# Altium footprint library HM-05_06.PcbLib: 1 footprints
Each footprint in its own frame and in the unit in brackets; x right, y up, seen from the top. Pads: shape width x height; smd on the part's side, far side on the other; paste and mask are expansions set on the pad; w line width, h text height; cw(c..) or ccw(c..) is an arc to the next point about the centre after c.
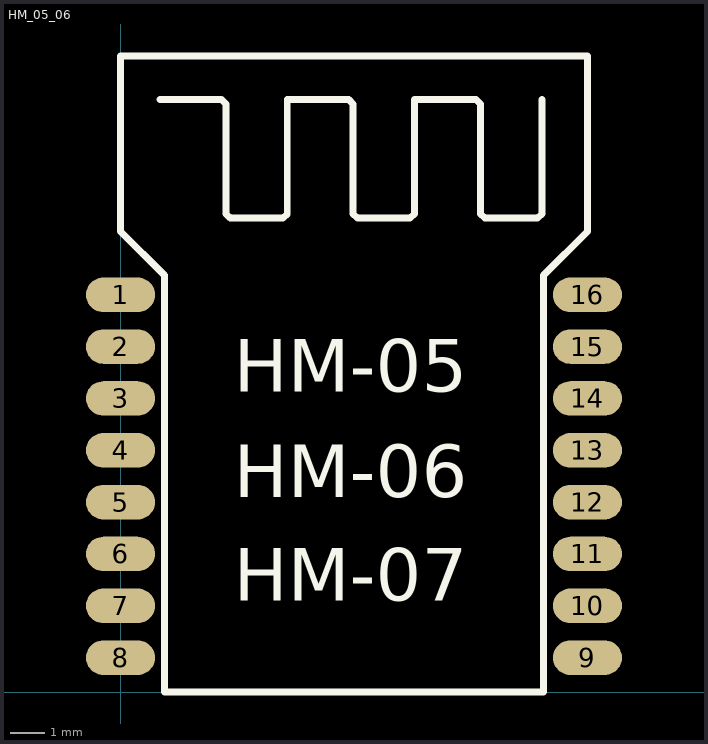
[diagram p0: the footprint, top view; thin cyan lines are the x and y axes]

## HM_05_06 [mm] "www.jnhuamao.cn"
pads (16):
  oval 2x1 smd: 1(0,11.5) 2(0,10) 3(0,8.5) 4(0,7) 5(0,5.5) 6(0,4) 7(0,2.5) 8(0,1) 9(13.513,1) 10(13.513,2.5) 11(13.513,4) 12(13.513,5.5) 13(13.513,7) 14(13.513,8.5) 15(13.513,10) 16(13.513,11.5)
Top Overlay:
  lines w0.2: 1.143,17.145 2.921,17.145 3.048,17.018 3.048,13.843 3.175,13.716 4.699,13.716 4.826,13.843 4.826,17.145 6.604,17.145 6.731,17.018 6.731,13.843 6.858,13.716 8.382,13.716 8.509,13.843 8.509,17.145 10.287,17.145 10.414,17.018 10.414,13.843 10.541,13.716 12.065,13.716 12.192,13.843 12.192,17.145 ; 0,13.335 0,18.415 13.513,18.415 13.513,13.335 12.243,12.065 12.243,0 1.27,0 1.27,12.065 0,13.335
  text "HM-07" at 3.277,2.642 h1.52
  text "HM-06" at 3.277,5.639 h1.52
  text "HM-05" at 3.277,8.687 h1.52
